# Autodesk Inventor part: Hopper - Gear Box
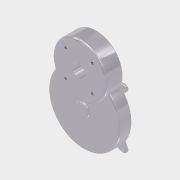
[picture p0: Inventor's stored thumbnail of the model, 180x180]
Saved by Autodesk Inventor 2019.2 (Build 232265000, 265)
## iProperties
Created: 2005-11
Part Number: Hopper - Gear Box
Document SubType Name: Modeling
Designer: floress
Material: Default
Density: 1 g/cm^3
Appearance: Aluminum - Polished
Author: floress
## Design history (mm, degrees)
sketch "Sketch1"
  geometry: C1 r 50.8 at (-2.495, 0); C2 r 38.1 at (-2.495, 50.8)
  constraints: 2 centre point, 1 vertical alignment
  dimensions: "d0" = 101.6 diameter of C1; "d1" = 76.2 diameter of C2; "d2" = 50.8 distance of C1.centre C2.centre
extrude "Extrusion1" new body sketch "Sketch1" distance "d3" = 19.05; taper "d4" = 0 deg
extrude "Extrusion2" join sketch "Sketch1" distance "d5" = 25.4; taper "d6" = 0 deg
sketch "Sketch2"
  geometry: L1 (-19.05, 19.05)-(19.05, -19.05); C1 r 38.1 at (0, 0) reference; C2 r 1.74 at (-19.05, 19.05); C3 r 1.74 at (19.05, 19.05); C4 r 1.74 at (19.05, -19.05); C5 r 1.74 at (-19.05, -19.05); C6 r 9.525 at (0, 0); 1 further point
  constraints: 5 centre point, 3 equal radius, 2 coincident, 2 end point, 2 horizontal alignment, 2 vertical alignment, 1 midpoint
  dimensions: "d7" = 3.4798 diameter of C2; "d8" = 38.1 distance of C5.centre L1.start; "d9" = 38.1 distance of L1.end C5.centre; "d10" = 19.05 diameter of C6
extrude "Extrusion3" cut sketch "Sketch2" distance "d11" = 12.7; taper "d12" = 0 deg
sketch "Sketch3"
  geometry: C1 r 7.938 at (2.495, 0); A1 r 50.8 centre (2.495, 0) between (-32.824, 36.513) and (37.815, 36.513) reference
  constraints: 1 centre point, 1 coincident
  dimensions: "d13" = 15.875 diameter of C1
extrude "Extrusion4" cut sketch "Sketch3" distance "d14" = 3.175; taper "d15" = 0 deg
sketch "Sketch4"
  geometry: C1 r 7.937 at (0, 0) reference; C2 r 6.35 at (0, 0)
  constraints: 1 centre point, 1 coincident
  dimensions: "d16" = 12.7 diameter of C2
extrude "Extrusion5" join sketch "Sketch4" distance "d17" = 9.525; taper "d18" = 0 deg
fillet "Fillet1" dims "d19" = 3.175
sketch "Sketch5"
  geometry: C1 r 9.525 at (-2.495, 0); A1 r 47.625 centre (-2.495, 0) between (-36.409, 33.437) and (31.418, 33.437) reference
  constraints: 1 centre point, 1 coincident
  dimensions: "d20" = 19.05 diameter of C1
extrude "Extrusion6" join sketch "Sketch5" distance "d21" = 3.2004; taper "d22" = 0 deg
fillet "Fillet2" dims "d23" = 1.5875
fillet "Fillet3" dims "d24" = 1.5875
sketch "Sketch6"
  geometry: C1 r 6.35 at (0, 0) reference; C2 r 1.422 at (0, 3.175); C3 r 1.422 at (0, -3.175)
  constraints: 2 centre point, 2 vertical alignment, 1 equal radius
  dimensions: "d26" = 2.8448 diameter of C2; "d27" = 3.175 distance of C1.centre C2.centre; "d28" = 3.175 distance of C1.centre C3.centre
extrude "Extrusion7" cut sketch "Sketch6" distance "d29" = 6.35; taper "d30" = 0 deg
sketch "Sketch7" dims "d51" = 111.125 (derived)
  geometry: L1 (2.495, 0)-(2.495, 18.663); L2 (2.495, 0)-(-14.291, 0); L3 (-38.317, 42.466)-(-34.682, 42.466); L4 (-41.685, 34.336)-(-38.009, 30.66); L5 (43.308, 42.466)-(39.673, 42.466); L6 (46.675, 34.336)-(43, 30.66); L7 (-42.642, -35.708)-(-39.413, -28.711); L8 (-36.67, -42.172)-(-29.44, -39.507); L9 (47.632, -35.708)-(44.404, -28.711); L10 (41.661, -42.172)-(34.43, -39.507); C1 r 1.778 at (-38.317, 37.703); C2 r 1.778 at (43.308, 37.703); C3 r 1.778 at (-38.317, -37.703); C4 r 1.778 at (43.308, -37.703); C5 r 7.937 at (2.495, 0) reference; A1 r 50.8 centre (2.495, 0) between (-32.824, 36.513) and (37.815, 36.513) reference; A2 r 38.1 centre (2.495, 50.8) between (37.815, 36.513) and (-32.824, 36.513) reference; A3 r 4.763 centre (-38.317, 37.703) between (-38.317, 42.466) and (-41.685, 34.336); A4 r 4.763 centre (-38.317, -37.703) between (-42.642, -35.708) and (-36.67, -42.172); A5 r 4.763 centre (43.308, 37.703) between (46.675, 34.336) and (43.308, 42.466); A6 r 4.763 centre (43.308, -37.703) between (41.661, -42.172) and (47.632, -35.708); A7 r 50.8 centre (2.495, 0) between (-39.413, -28.711) and (-29.44, -39.507); A8 r 50.8 centre (2.495, 0) between (34.43, -39.507) and (44.404, -28.711); A9 r 50.8 centre (2.495, 0) between (-32.824, 36.513) and (-38.009, 30.66); A10 r 50.8 centre (2.495, 0) between (43, 30.66) and (37.815, 36.513); A11 r 38.1 centre (2.495, 50.8) between (-34.682, 42.466) and (-32.824, 36.513); A12 r 38.1 centre (2.495, 50.8) between (37.815, 36.513) and (39.673, 42.466); 1 further point
  constraints: 24 point on circle, 20 end point, 14 centre point, 13 symmetric about line, 11 coincident, 6 tangent, 1 equal radius, 1 parallel, 1 perpendicular, 1 vertical, 8 other
  dimensions: "d31" = 9.525 diameter of A3; "d32" = 45 deg angle of L4 L3; "d33" = 3.556 diameter of C1
extrude "Extrusion8" join sketch "Sketch7" distance "d36" = 3.175; taper "d37" = 0 deg
fillet "Fillet5" dims "d38" = 1.5875
thread "Thread1" dims "d39" = 25.4, "d40" = 0
thread "Thread2" dims "d41" = 25.4, "d42" = 0
thread "Thread3" dims "d43" = 25.4, "d44" = 0
thread "Thread4" dims "d45" = 25.4, "d46" = 0
thread "Thread5" dims "d47" = 25.4, "d48" = 0
thread "Thread6" dims "d49" = 25.4, "d50" = 0
body "Solid1"
